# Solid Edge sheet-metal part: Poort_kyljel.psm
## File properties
Author: haldur
Template: Normal.psm
Last saved by: haldur
Revision: 4
Application: Solid Edge
Accuracy: 0,990
Material Thickness: 0,20 mm
Bend Radius: 1,00 mm
Relief Width: 1,00 mm
Relief Length: 0,00 mm
Neutral Factor: 0,330
Minimum Arc Length: 0,10 mm
Deviational Tolerance: 0,10 mm
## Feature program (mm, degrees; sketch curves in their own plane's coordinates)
base tab "unnamed BaseTab 1"
sketch for "unnamed Cutout 1" #1 plane through (48.8541, 0, 2) normal (0, -1, 0) x-axis (1, 0, 0)
  line (-106.5964, -2) -> (-106.5964, -0.5042)
  line (-106.5964, -0.5042) -> (-103.2536, -0.5042)
  line (-103.2536, -0.5042) -> (-103.2536, -2)
  line (-103.2536, -2) -> (-106.5964, -2)
sketch for "unnamed Cutout 1" #2 plane through (48.8541, 0, 2) normal (0, -1, 0) x-axis (1, 0, 0)
  line (-106.5964, 1.6974) -> (-106.5964, -0.1814)
  line (-106.5964, -0.1814) -> (-103.2536, -0.1814)
  line (-103.2536, -0.1814) -> (-103.2536, 1.6974)
  line (-103.2536, 1.6974) -> (-106.5964, 1.6974)
extrude "unnamed Cutout 1" cut
extrude "unnamed Cutout 2" cut
extrude "unnamed Cutout 3" cut
extrude "unnamed Cutout 4" cut
extrude "unnamed Cutout 5" cut
extrude "unnamed Cutout 6" cut
extrude "unnamed Cutout 7" cut
extrude "unnamed Cutout 8" cut
extrude "unnamed Cutout 9" cut
extrude "unnamed Cutout 10" cut
extrude "unnamed Cutout 11" cut
extrude "unnamed Cutout 12" cut
extrude "unnamed Cutout 13" cut
extrude "unnamed Cutout 14" cut
extrude "unnamed Cutout 15" cut
extrude "unnamed Cutout 16" cut
extrude "unnamed Cutout 17" cut
extrude "unnamed Cutout 18" cut
extrude "unnamed Cutout 19" cut
extrude "unnamed Cutout 20" cut
extrude "unnamed Cutout 21" cut
extrude "unnamed Cutout 22" cut
extrude "unnamed Cutout 23" cut
extrude "unnamed Cutout 24" cut
extrude "unnamed Cutout 25" cut
extrude "unnamed Cutout 26" cut
extrude "unnamed Cutout 27" cut
extrude "unnamed Cutout 28" cut
extrude "unnamed Cutout 29" cut
extrude "unnamed Cutout 30" cut
extrude "unnamed Cutout 31" cut
extrude "unnamed Cutout 32" cut
extrude "unnamed Cutout 33" cut
extrude "unnamed Cutout 34" cut
extrude "unnamed Cutout 35" cut
extrude "unnamed Cutout 36" cut
extrude "unnamed Cutout 37" cut
extrude "unnamed Cutout 38" cut
extrude "unnamed Cutout 39" cut
extrude "unnamed Cutout 40" cut
extrude "unnamed Cutout 41" cut
extrude "unnamed Cutout 42" cut
extrude "unnamed Cutout 43" cut
extrude "unnamed Cutout 44" cut
extrude "unnamed Cutout 45" cut
extrude "unnamed Cutout 46" cut
extrude "unnamed Cutout 47" cut
extrude "unnamed Cutout 48" cut
extrude "unnamed Cutout 49" cut
extrude "unnamed Cutout 50" cut
extrude "unnamed Cutout 51" cut
extrude "unnamed Cutout 52" cut
extrude "unnamed Cutout 53" cut
extrude "unnamed Cutout 54" cut
extrude "unnamed Cutout 55" cut
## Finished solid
Body 1: solid body, 446 faces, 1332 edges, 888 vertices.
  Faces by surface: plane 446
  Edges by curve: line 1332
Bounding box of the edges (mm): 213.850 x 0.200 x 4.000, from (-58.0709, 0, 0) to (155.7791, 0.2, 4).
Planar faces by outward normal: +x 111, +y 1, +z 56, -x 111, -y 1, -z 166
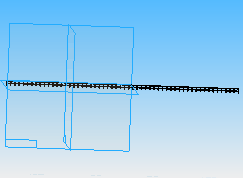
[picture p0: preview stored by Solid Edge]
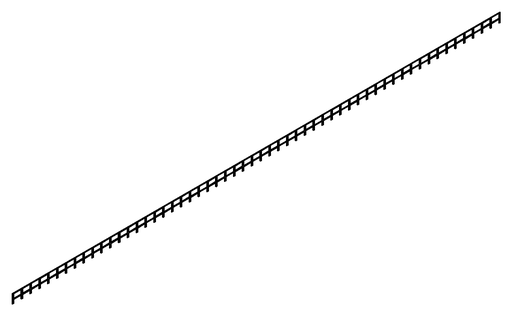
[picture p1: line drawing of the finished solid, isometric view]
